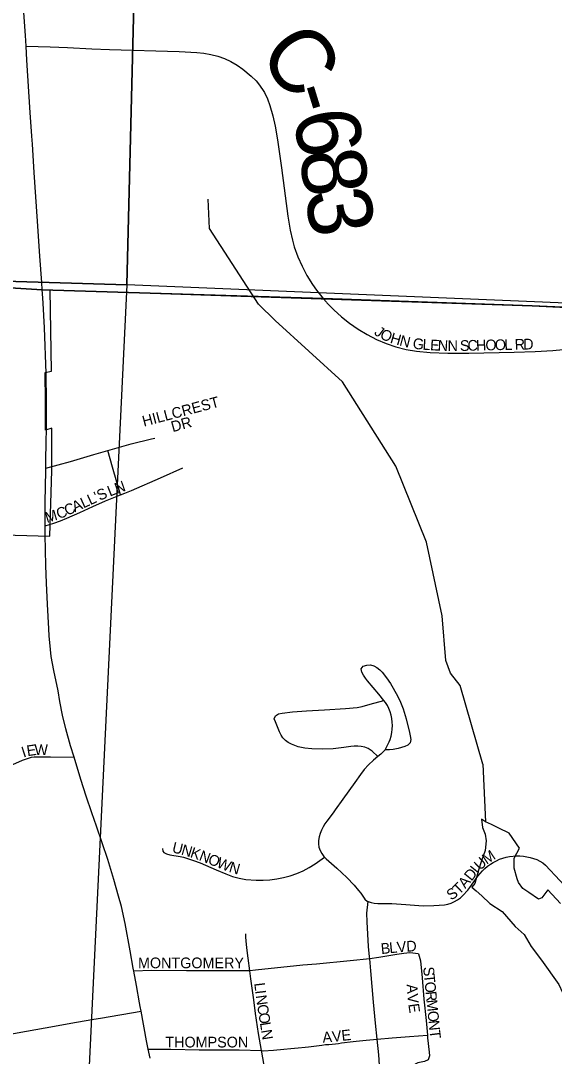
# Model space of a CAD drawing. Extents: x 0 to 34, y 0 to 22.
# Drawn here: x 27.584 to 28.055, y 17.603 to 18.518 of the extents above; entities that cross this region are included whole.
import ezdxf

# ---------------------------------------------------------------- set-up
doc = ezdxf.new("R2010")
doc.units = 0
for name, color, linetype in [('GM_X_City_Street', 7, 'Continuous'), ('GM_X_City_Street_Text', 7, 'Continuous'), ('GM_X_Corporation', 7, 'Continuous'), ('GM_X_County_Road', 7, 'Continuous'), ('GM_X_County_Road_Text', 7, 'Continuous'), ('GM_X_Minor_Lake', 7, 'Continuous'), ('GM_X_Minor_River', 7, 'Continuous'), ('GM_X_Section', 7, 'Continuous'), ('GM_X_State_Route', 7, 'Continuous'), ('GM_X_Township', 7, 'Continuous')]:
    doc.layers.add(name, color=color, linetype=linetype)

msp = doc.modelspace()

# ---------------------------------------------------------------- linework, layer by layer
at = {"layer": 'GM_X_City_Street'}
for points in [[(27.85393, 18.26885), (27.85999, 18.26259), (27.86684, 18.25642), (27.8741, 18.25072), (27.88171, 18.24549), (27.8896, 18.24071), (27.89778, 18.23644), (27.90626, 18.23284), (27.91499, 18.22991), (27.92391, 18.22763), (27.93299, 18.22608), (27.94524, 18.22494), (27.96066, 18.22431), (27.9792, 18.22428), (28.01942, 18.22523), (28.03796, 18.22566), (28.05337, 18.22652), (28.0718, 18.22836), (28.0813, 18.22968), (28.08427, 18.23019), (28.08748, 18.23074), (28.09309, 18.23181), (28.1176, 18.23769), (28.13753, 18.24213)], [(27.66046, 18.13826), (27.6811, 18.14413), (27.69916, 18.14863), (27.70221, 18.14927)], [(27.60579, 18.12257), (27.6275, 18.1287), (27.63643, 18.13134), (27.64833, 18.13482), (27.66046, 18.13826)], [(27.6717, 18.09901), (27.66469, 18.12342), (27.66046, 18.13826)], [(27.6717, 18.09901), (27.67574, 18.10064), (27.68142, 18.10289), (27.70697, 18.11407), (27.72679, 18.12296)], [(27.60535, 18.07177), (27.61295, 18.07411), (27.61878, 18.07616), (27.62453, 18.07851), (27.63586, 18.08366), (27.6472, 18.08876), (27.65857, 18.09371), (27.6717, 18.09901)], [(27.90441, 17.91753), (27.89996, 17.923), (27.8899, 17.93485), (27.88797, 17.93729), (27.88621, 17.93985), (27.88483, 17.94261), (27.8844, 17.94556), (27.88614, 17.94769), (27.88923, 17.94879), (27.89247, 17.94881), (27.8954, 17.94796), (27.89814, 17.94655), (27.90067, 17.94466), (27.9029, 17.94249), (27.90677, 17.9376), (27.91018, 17.93238), (27.91626, 17.92153), (27.91901, 17.91595), (27.92133, 17.91019), (27.92402, 17.90127), (27.927, 17.88919), (27.92763, 17.88614), (27.92802, 17.88305), (27.9276, 17.88001), (27.92559, 17.87795), (27.92275, 17.87692), (27.91686, 17.87498), (27.91258, 17.87407), (27.90923, 17.87378), (27.9055, 17.87399)], [(27.89902, 17.86792), (27.89397, 17.87267), (27.89034, 17.87513), (27.88744, 17.87626), (27.88439, 17.87691), (27.88127, 17.87714), (27.87817, 17.87708), (27.87506, 17.87679), (27.86886, 17.87592), (27.85955, 17.87471), (27.85018, 17.87434), (27.84084, 17.87463), (27.83462, 17.87522), (27.83156, 17.87583), (27.82854, 17.87665), (27.8256, 17.87768), (27.82271, 17.87888), (27.81993, 17.88031), (27.81739, 17.88211), (27.81523, 17.88436), (27.81351, 17.88696), (27.81212, 17.88976), (27.80986, 17.89559), (27.80853, 17.8985), (27.80747, 17.90137), (27.80852, 17.90391), (27.81126, 17.90566), (27.81441, 17.90627), (27.82371, 17.90729), (27.83614, 17.90844), (27.85177, 17.90924), (27.8705, 17.91033), (27.88062, 17.9113), (27.88519, 17.91202), (27.89228, 17.91411), (27.90441, 17.91753)], [(27.9055, 17.87399), (27.90905, 17.88085), (27.90998, 17.8831), (27.91086, 17.88605), (27.91143, 17.88906), (27.91176, 17.89213), (27.91185, 17.89524), (27.91169, 17.89834), (27.91129, 17.90142), (27.9107, 17.90445), (27.90989, 17.90744), (27.90883, 17.91035), (27.90748, 17.91315), (27.90583, 17.91578), (27.90441, 17.91753)], [(27.5316, 17.86006), (27.53621, 17.8594), (27.54244, 17.859), (27.55182, 17.85887), (27.56434, 17.85906), (27.57056, 17.85951), (27.57361, 17.86008), (27.57659, 17.86099), (27.58524, 17.86465), (27.59314, 17.86742), (27.59554, 17.86765), (27.60988, 17.86768), (27.63074, 17.8673)], [(27.89902, 17.86792), (27.89515, 17.86461), (27.89064, 17.86067), (27.88692, 17.85652), (27.88362, 17.85217), (27.87865, 17.84504), (27.86821, 17.83042), (27.86123, 17.82075), (27.85947, 17.81826), (27.85399, 17.81091), (27.85221, 17.80837), (27.85058, 17.80571), (27.84913, 17.80292), (27.84795, 17.8), (27.84713, 17.79694), (27.84671, 17.79379), (27.84672, 17.79078), (27.84703, 17.78795), (27.84797, 17.78495), (27.8494, 17.78219), (27.85118, 17.77968), (27.8518, 17.77907)], [(27.9055, 17.87399), (27.90162, 17.87016), (27.89902, 17.86792)], [(27.70884, 17.78674), (27.70924, 17.78447), (27.70999, 17.78327), (27.71242, 17.78186), (27.71534, 17.78112), (27.72446, 17.77956), (27.7275, 17.77892), (27.73634, 17.77621), (27.74224, 17.77419), (27.75634, 17.7679), (27.76478, 17.7642), (27.77054, 17.76212), (27.77642, 17.76045), (27.78241, 17.75938), (27.79153, 17.75864), (27.79762, 17.75863), (27.80373, 17.75902), (27.80978, 17.75979), (27.81579, 17.76095), (27.82169, 17.76254), (27.82743, 17.7646), (27.833, 17.76707), (27.83837, 17.76996), (27.84355, 17.77319), (27.8518, 17.77907)], [(27.8518, 17.77907), (27.85337, 17.77752), (27.86276, 17.76941), (27.87172, 17.76099), (27.87811, 17.75435), (27.88206, 17.74963), (27.88387, 17.74715), (27.88561, 17.74459), (27.88752, 17.74208), (27.88998, 17.74002), (27.89036, 17.73989)], [(27.89036, 17.73989), (27.89297, 17.739), (27.89579, 17.73853), (27.89888, 17.73825), (27.91122, 17.73799), (27.92357, 17.7372), (27.93907, 17.73621), (27.94841, 17.73626), (27.95773, 17.73687), (27.96084, 17.73742), (27.96385, 17.73843), (27.96665, 17.73982), (27.96931, 17.74144), (27.97183, 17.74325), (27.97416, 17.7453), (27.97834, 17.74978), (27.9802, 17.75223), (27.98369, 17.75732), (27.98733, 17.76228), (27.99138, 17.76691), (27.99358, 17.76903), (27.99593, 17.771), (27.99839, 17.77283), (28.00096, 17.77449), (28.00364, 17.77595), (28.00644, 17.77718), (28.00933, 17.77823), (28.01226, 17.77907), (28.01525, 17.77964), (28.02137, 17.78014), (28.02442, 17.78012), (28.02747, 17.77988), (28.03051, 17.77945), (28.03351, 17.77881), (28.03647, 17.77799), (28.03933, 17.77694), (28.04205, 17.77561), (28.04459, 17.774), (28.04689, 17.77203), (28.0723, 17.7449)], [(27.89179, 17.68911), (27.89163, 17.69091), (27.89087, 17.70015), (27.88959, 17.7218), (27.88934, 17.72969), (27.89036, 17.73989)], [(27.78589, 17.67875), (27.78442, 17.68986), (27.78336, 17.69906), (27.78273, 17.70519), (27.78251, 17.70825), (27.78242, 17.71131)], [(27.93483, 17.69362), (27.92736, 17.69444), (27.92197, 17.69398), (27.91565, 17.69308), (27.89986, 17.69032), (27.89179, 17.68911)], [(27.93483, 17.69362), (27.93657, 17.68753), (27.93818, 17.6724), (27.93971, 17.65365), (27.94162, 17.63492), (27.94276, 17.62192)], [(27.89179, 17.68911), (27.87469, 17.68746), (27.84473, 17.68456), (27.8327, 17.68352), (27.79104, 17.67918), (27.78589, 17.67875)], [(27.89837, 17.61827), (27.89697, 17.63241), (27.89515, 17.65094), (27.89273, 17.67862), (27.89179, 17.68911)], [(27.78589, 17.67875), (27.78292, 17.67851), (27.73002, 17.6786), (27.69901, 17.67882), (27.68359, 17.67824)], [(27.79636, 17.60813), (27.79374, 17.6234), (27.79104, 17.64108), (27.78948, 17.65317), (27.78685, 17.6715), (27.78589, 17.67875)], [(27.56966, 17.62172), (27.58068, 17.62392), (27.60526, 17.62834), (27.63288, 17.63318), (27.64818, 17.63586), (27.6542, 17.63689), (27.68992, 17.64309)], [(27.89837, 17.61827), (27.91151, 17.61944), (27.92687, 17.62073), (27.94276, 17.62192)], [(27.94276, 17.62192), (27.94298, 17.61935), (27.94431, 17.60685), (27.94453, 17.60363), (27.9435, 17.60014), (27.9403, 17.59844), (27.93417, 17.5975), (27.93196, 17.5962), (27.93068, 17.59399), (27.93028, 17.59113), (27.93068, 17.58493), (27.93168, 17.57562), (27.93229, 17.57134), (27.93254, 17.56652)], [(27.69629, 17.60955), (27.71625, 17.60938), (27.74115, 17.60885), (27.77643, 17.60872), (27.79636, 17.60813)], [(27.79636, 17.60813), (27.79766, 17.6081), (27.80688, 17.60871), (27.81612, 17.60941), (27.82225, 17.61005), (27.82851, 17.61064), (27.8348, 17.61126), (27.83784, 17.6116), (27.84966, 17.61294), (27.85275, 17.61345), (27.85585, 17.61362), (27.85867, 17.61391), (27.86174, 17.61416), (27.86439, 17.6146), (27.86684, 17.61497), (27.86947, 17.61532), (27.87448, 17.61591), (27.8771, 17.61618), (27.87986, 17.61644), (27.88276, 17.61672), (27.88575, 17.617), (27.88879, 17.6173), (27.89191, 17.61762), (27.89837, 17.61827)], [(27.90248, 17.56245), (27.89975, 17.60452), (27.89837, 17.61827)], [(27.80615, 17.53778), (27.80488, 17.54876), (27.80351, 17.56103), (27.80195, 17.57334), (27.80059, 17.58256), (27.79924, 17.5917), (27.7966, 17.60671), (27.79636, 17.60813)]]:
    msp.add_lwpolyline(points, dxfattribs=at)
at = {"layer": 'GM_X_Corporation'}
msp.add_lwpolyline([(27.50706, 18.06564), (27.60948, 18.06256), (27.61116, 18.12049), (27.61116, 18.15798), (27.60564, 18.15628), (27.60565, 18.18117), (27.60524, 18.20728), (27.61083, 18.20833), (27.60953, 18.28012), (28.03523, 18.26605), (28.13337, 18.26149), (28.25997, 18.25738), (28.33724, 18.14128), (28.33966, 18.07033), (28.43214, 18.05835), (28.55968, 17.79037), (28.47825, 17.79119), (28.47781, 17.74759), (28.48568, 17.74233), (28.48869, 17.60507), (28.54513, 17.60631)], dxfattribs=at)
msp.add_lwpolyline([(27.50706, 18.06564), (27.60948, 18.06256), (27.61116, 18.12049), (27.61116, 18.15798), (27.60564, 18.15628), (27.60565, 18.18117), (27.60524, 18.20728), (27.61083, 18.20833), (27.60953, 18.28012), (28.03523, 18.26605), (28.13337, 18.26149), (28.25997, 18.25738), (28.33724, 18.14128), (28.33966, 18.07033), (28.43214, 18.05835), (28.55968, 17.79037), (28.47825, 17.79119), (28.47781, 17.74759), (28.48568, 17.74233), (28.48869, 17.60507), (28.54513, 17.60631)], dxfattribs=at)
at = {"layer": 'GM_X_County_Road'}
msp.add_lwpolyline([(27.58844, 18.49557), (27.60962, 18.49476), (27.62507, 18.49422), (27.64661, 18.49319), (27.66199, 18.49246), (27.72371, 18.49059), (27.7392, 18.48985), (27.74542, 18.48924), (27.75159, 18.48819), (27.75766, 18.4866), (27.76357, 18.48447), (27.76925, 18.48181), (27.77465, 18.47863), (27.77978, 18.47504), (27.78705, 18.46909), (27.79152, 18.46468), (27.79359, 18.46232), (27.79729, 18.45724), (27.79888, 18.45452), (27.80157, 18.44884), (27.80371, 18.44295), (27.80632, 18.43397), (27.8084, 18.42487), (27.81052, 18.41263), (27.81382, 18.38808), (27.81945, 18.34515), (27.82151, 18.33299), (27.8235, 18.32398), (27.82517, 18.31807), (27.82829, 18.30943), (27.83209, 18.30104), (27.83643, 18.2929), (27.84122, 18.28502), (27.84471, 18.27999), (27.85085, 18.27245), (27.85357, 18.26922), (27.85393, 18.26885)], dxfattribs=at)
at = {"layer": 'GM_X_Minor_Lake'}
for points in [[(27.99403, 17.81025), (27.99061, 17.8125), (27.99142, 17.8053), (27.99374, 17.79924), (27.99454, 17.79355), (27.99385, 17.78482), (27.99051, 17.77568), (27.98792, 17.76769), (27.9846, 17.7559), (27.98197, 17.75246), (27.98578, 17.74945), (27.99074, 17.74493), (27.99799, 17.73815), (28.00866, 17.73101), (28.02012, 17.71781), (28.02814, 17.71066), (28.03428, 17.70007), (28.04347, 17.68799), (28.05879, 17.66646), (28.06533, 17.65246), (28.0695, 17.65287), (28.07745, 17.65444), (28.08615, 17.65527), (28.09255, 17.66176)], [(28.06014, 17.73822), (28.04906, 17.75028), (28.04831, 17.74914), (28.04381, 17.74304), (28.04078, 17.74187), (28.0324, 17.74789), (28.02707, 17.75127), (28.02324, 17.75655), (28.02208, 17.75996), (28.01935, 17.76943), (28.01929, 17.77816), (28.02415, 17.78693), (28.01495, 17.80015), (28.00582, 17.80464), (27.99936, 17.80801), (27.99403, 17.81025)]]:
    msp.add_lwpolyline(points, dxfattribs=at)
at = {"layer": 'GM_X_Minor_River'}
for points in [[(27.99173, 17.86109), (27.9717, 17.93063), (27.96326, 17.94153), (27.95898, 17.95286), (27.95591, 17.99226), (27.94198, 18.05732), (27.91478, 18.12451), (27.86784, 18.19907), (27.80825, 18.25302), (27.79372, 18.26765), (27.75027, 18.33428), (27.74923, 18.36043)], [(27.99173, 17.86109), (27.99403, 17.81025)]]:
    msp.add_lwpolyline(points, dxfattribs=at)
at = {"layer": 'GM_X_Section'}
for points in [[(27.70209, 19.27644), (27.6773, 18.28453), (26.67748, 18.31474), (26.71012, 19.30514)], [(28.70052, 19.24223), (28.6651, 18.24345), (27.6773, 18.28453), (27.70209, 19.27644)], [(26.67748, 18.31474), (27.6773, 18.28453), (27.62712, 17.24067), (26.63943, 17.27671)]]:
    msp.add_lwpolyline(points, close=True, dxfattribs=at)
at = {"layer": 'GM_X_State_Route'}
for points in [[(27.59354, 18.41583), (27.59211, 18.43673), (27.5892, 18.48314), (27.58844, 18.49557), (27.58787, 18.5048), (27.58644, 18.52529)], [(27.6061, 18.20647), (27.60477, 18.2467), (27.60353, 18.26845), (27.6029, 18.27686), (27.60272, 18.28017), (27.60228, 18.28664), (27.60065, 18.30992), (27.59843, 18.34091), (27.59565, 18.38375), (27.59402, 18.40883), (27.59354, 18.41583)], [(27.60647, 18.15653), (27.60647, 18.15656), (27.60648, 18.18144), (27.6061, 18.2063), (27.6061, 18.20647)], [(27.60627, 18.14654), (27.60647, 18.15653)], [(27.60538, 18.06577), (27.60535, 18.07177), (27.60531, 18.08266), (27.60517, 18.09492), (27.60541, 18.1041), (27.60579, 18.12257), (27.60591, 18.12862), (27.60627, 18.14654)], [(27.63074, 17.8673), (27.62772, 17.87732), (27.6235, 17.8923), (27.62059, 17.90442), (27.61832, 17.91666), (27.61672, 17.92584), (27.61303, 17.94406), (27.61068, 17.95624), (27.6099, 17.96236), (27.6088, 17.97463), (27.60837, 17.98078), (27.60739, 18.00247), (27.60658, 18.02109), (27.60599, 18.03663), (27.60538, 18.0638), (27.60538, 18.06577)], [(27.69796, 17.60151), (27.69629, 17.60955), (27.69479, 17.61673), (27.68992, 17.64309), (27.68913, 17.64729), (27.68862, 17.65036), (27.68598, 17.66563), (27.68359, 17.67824), (27.68309, 17.68089), (27.68036, 17.69619), (27.67599, 17.72058), (27.67253, 17.73562), (27.67011, 17.74455), (27.66593, 17.75944), (27.66053, 17.77713), (27.65568, 17.79181), (27.6507, 17.80648), (27.64661, 17.81821), (27.64148, 17.83288), (27.63668, 17.84763), (27.63074, 17.8673)]]:
    msp.add_lwpolyline(points, dxfattribs=at)
at = {"layer": 'GM_X_Township'}
for points in [[(26.64338, 18.32213), (26.64994, 18.32195), (26.65415, 18.32164), (26.6574, 18.3212), (26.66046, 18.32066), (26.66345, 18.31987), (26.93903, 18.30939), (27.3097, 18.29835), (27.60273, 18.28017), (27.85085, 18.27245), (28.03523, 18.26605), (28.13527, 18.2617), (28.25997, 18.25738), (28.66555, 18.2443), (28.72626, 19.93416)], [(28.59551, 16.41415), (28.59908, 16.58872), (28.59988, 16.61088), (28.63677, 17.49807), (28.63701, 17.50604), (28.6433, 17.85758), (28.66555, 18.2443), (28.25997, 18.25738), (28.13527, 18.2617), (28.03523, 18.26605), (27.85085, 18.27245), (27.60273, 18.28017), (27.3097, 18.29835), (26.93903, 18.30939), (26.66345, 18.31987), (26.66046, 18.32066), (26.6574, 18.3212), (26.65415, 18.32164), (26.64994, 18.32195), (26.64338, 18.32213)]]:
    msp.add_lwpolyline(points, dxfattribs=at)

# ---------------------------------------------------------------- texts
at = {"layer": 'GM_X_City_Street_Text'}
for s, rotation, p in [('J', 323.21751, (27.89506, 18.24134)), ('O', 334.15023, (27.90008, 18.23782)), ('H', 344.03116, (27.90925, 18.23355)), ('N', 345.41838, (27.9175, 18.2312)), ('G', 353.51387, (27.92944, 18.22833)), ('L', 356.26581, (27.93822, 18.22734)), ('E', 356.57027, (27.94492, 18.22691)), ('N', 357.15563, (27.95168, 18.2265)), ('N', 0.37536, (27.96059, 18.22607)), ('S', 1.24955, (27.97158, 18.22618)), ('C', 1.24071, (27.97824, 18.22633)), ('H', 1.27695, (27.98574, 18.22649)), ('O', 1.24632, (27.99407, 18.22668)), ('O', 1.24382, (28.0024, 18.22686)), ('L', 1.276, (28.01073, 18.22704)), ('R', 1.26332, (28.0199, 18.22724)), ('D', 1.48051, (28.02744, 18.2274)), ('HILLCREST', 14.78375, (27.6924, 18.1593)), ('DR', 15.52912, (27.71789, 18.15443)), ('S', 24.68357, (27.65342, 18.09368)), ('L', 21.57308, (27.66239, 18.09748)), ('N', 19.45094, (27.6685, 18.0999)), ('A', 24.69686, (27.63145, 18.08358)), ('L', 24.71647, (27.63903, 18.08706)), ('L', 24.68357, (27.64508, 18.08985)), ("'", 24.7422, (27.65115, 18.09264)), ('M', 16.66087, (27.60676, 18.07422)), ('C', 22.35821, (27.61732, 18.07743)), ('C', 24.64702, (27.62463, 18.08045)), ('I', 17.85455, (27.58605, 17.86698)), ('E', 8.55508, (27.58963, 17.86817)), ('W', 0.79012, (27.59588, 17.86913)), ('U', 346.74822, (27.71678, 17.78341)), ('N', 343.43896, (27.72475, 17.78154)), ('K', 341.4545, (27.73265, 17.77919)), ('N', 339.19321, (27.74046, 17.77657)), ('M', 33.14451, (27.99498, 17.7723)), ('O', 338.07278, (27.7482, 17.77363)), ('W', 338.22544, (27.75596, 17.77051)), ('N', 343.4032, (27.7669, 17.76618)), ('U', 43.50109, (27.98929, 17.76684)), ('D', 50.99268, (27.98164, 17.75737)), ('I', 51.02661, (27.98689, 17.76385)), ('T', 44.338, (27.9707, 17.74544)), ('A', 49.9658, (27.97616, 17.75084)), ('S', 33.34911, (27.96359, 17.74053)), ('B', 5.44954, (27.90203, 17.69344)), ('L', 5.44422, (27.90949, 17.69415)), ('V', 5.44965, (27.91613, 17.69478)), ('D', 2.44779, (27.9243, 17.69556)), ('MONTGOMERY', 0.00001, (27.68722, 17.68095)), ('S', 275.58282, (27.93899, 17.68184)), ('T', 275.63283, (27.93964, 17.6752)), ('L', 276.79286, (27.78982, 17.6677)), ('A', 273.54362, (27.9244, 17.66664)), ('O', 275.60404, (27.94029, 17.66857)), ('I', 276.74559, (27.79061, 17.66109)), ('N', 278.1356, (27.79113, 17.6567)), ('V', 275.60719, (27.92495, 17.65795)), ('R', 275.59461, (27.94111, 17.66027)), ('C', 279.04192, (27.79232, 17.64829)), ('E', 278.60291, (27.92583, 17.64912)), ('M', 275.61795, (27.94184, 17.6528)), ('O', 279.04195, (27.79351, 17.64088)), ('O', 275.60404, (27.94282, 17.64285)), ('L', 278.99079, (27.79481, 17.63267)), ('N', 275.60719, (27.94363, 17.63456)), ('THOMPSON', 0.00001, (27.71139, 17.61095)), ('N', 279.06297, (27.79586, 17.62607)), ('A', 4.54953, (27.85042, 17.61511)), ('V', 5.92556, (27.85898, 17.61579)), ('E', 6.68446, (27.86741, 17.61667)), ('T', 276.94759, (27.94447, 17.62602))]:
    msp.add_text(s, height=0.00947, rotation=rotation, dxfattribs=at).set_placement(p)
at = {"layer": 'GM_X_County_Road_Text'}
for s, rotation, p in [('C', 306.98106, (27.79204, 18.48824)), ('-', 287.16396, (27.81755, 18.45584)), ('6', 279.64648, (27.82392, 18.43566)), ('8', 277.56235, (27.82965, 18.40197)), ('3', 278.90917, (27.83444, 18.3661))]:
    msp.add_text(s, height=0.05682, rotation=rotation, dxfattribs=at).set_placement(p)

doc.saveas('drawing.dxf')
